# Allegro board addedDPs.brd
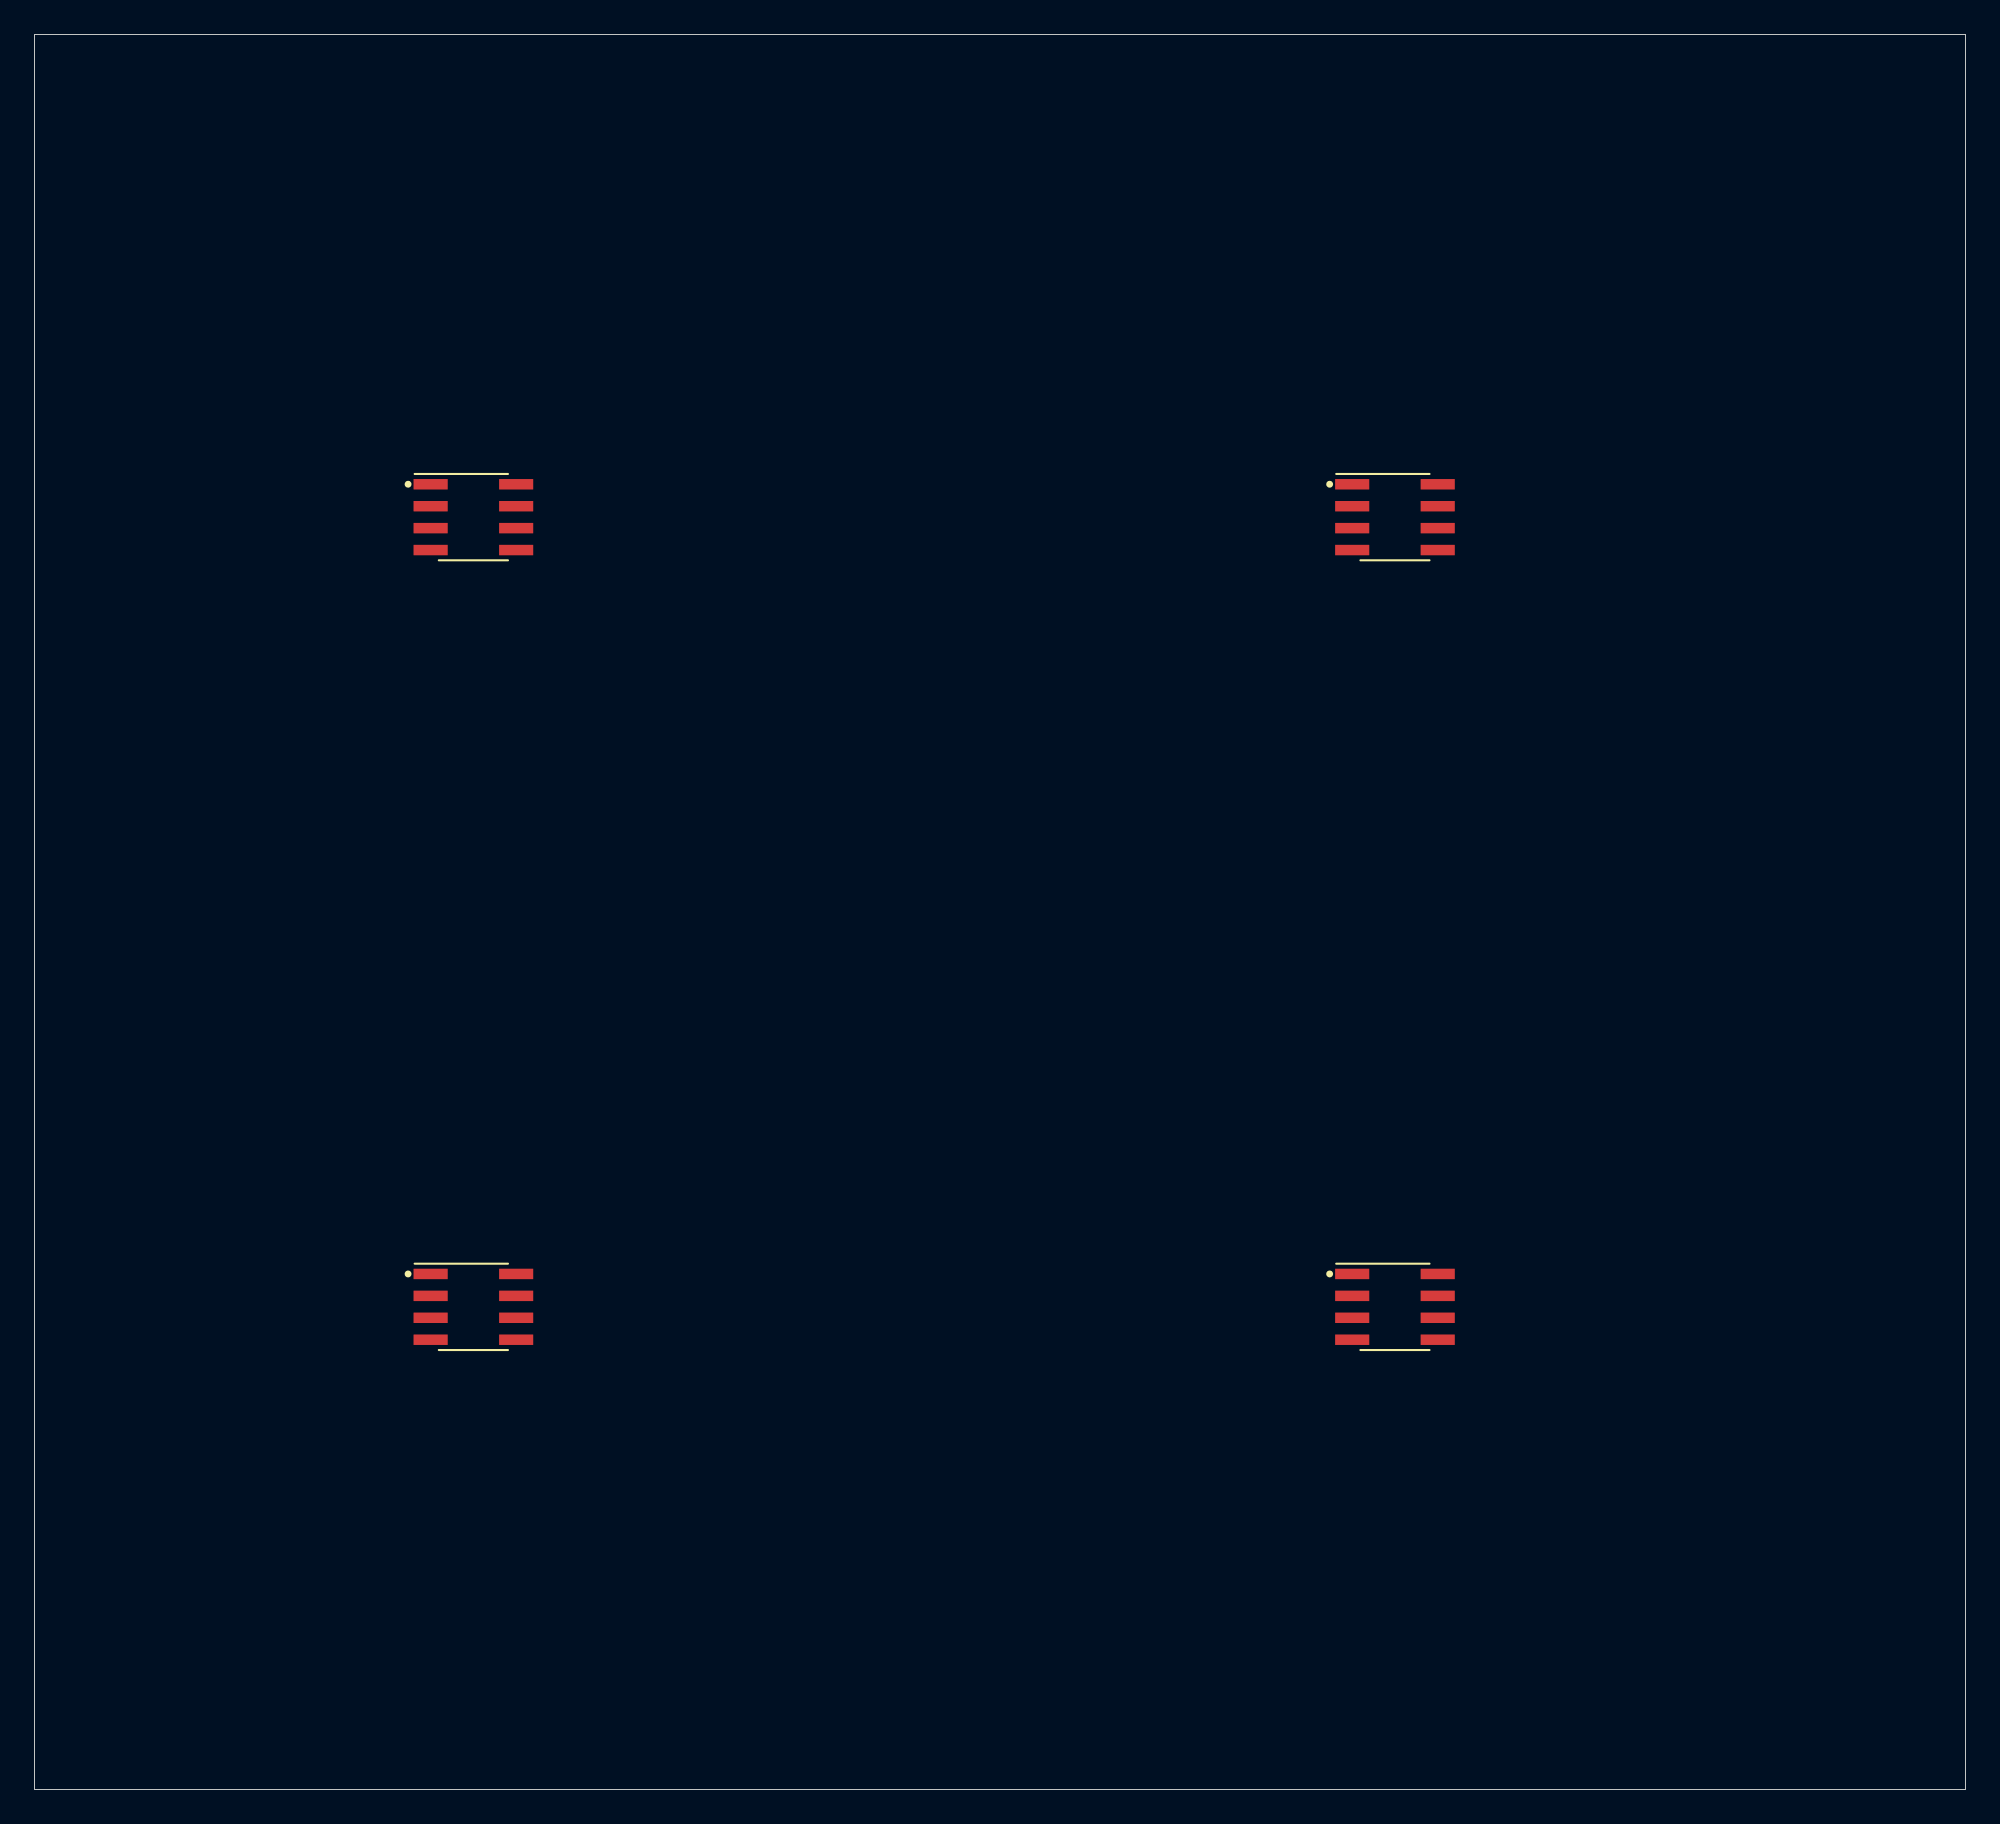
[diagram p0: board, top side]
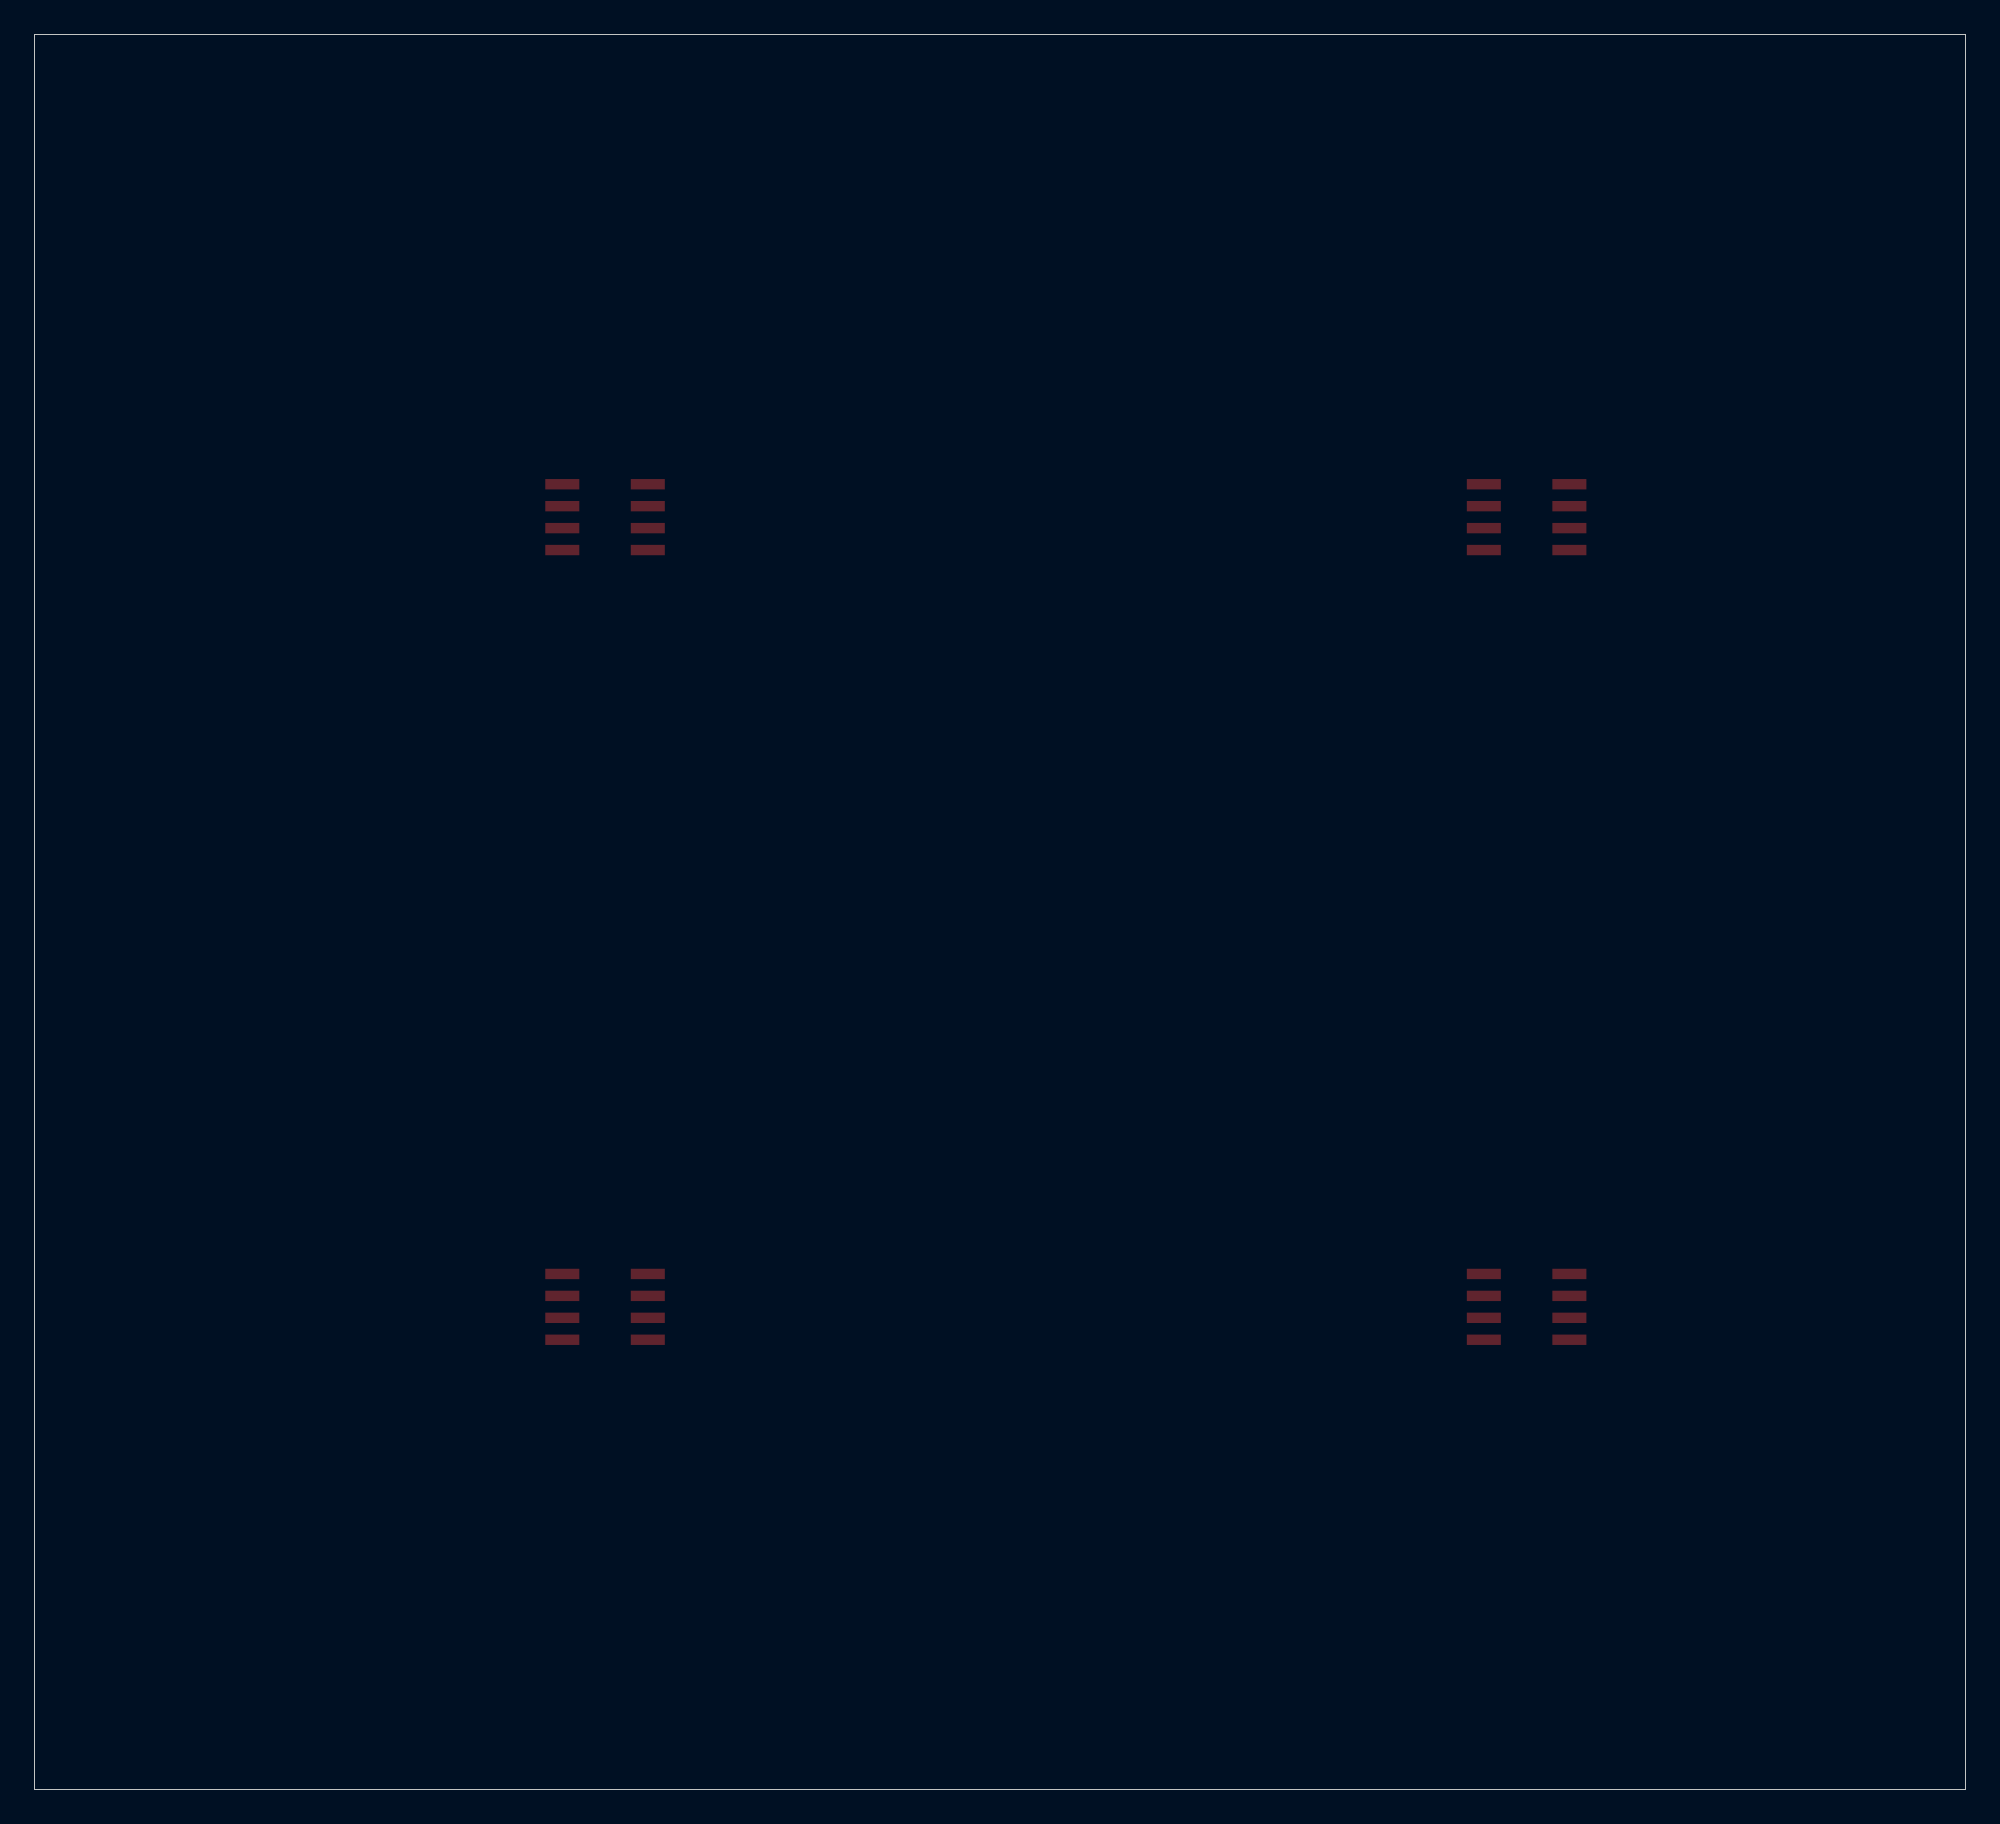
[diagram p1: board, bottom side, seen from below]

Outline 111.76 x 101.6 mm; copper layers: TOP, GND, VCC, BOTTOM. Coordinates in mm from the lower left corner of the outline.
Outline path: 0,101.6 0,0 111.76,0 111.76,101.6 0,101.6

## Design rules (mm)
net group D1: nets D1N D1P
net group D2: nets D2N D2P
net group D3: nets D3N D3P
net group D4: nets D4N D4P

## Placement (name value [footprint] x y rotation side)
U1  DS89C21  [SOIC127P600X175-8L87N]  25.4 73.66 270 top
U2  DS89C21  [SOIC127P600X175-8L87N]  78.74 73.66 270 top
U3  DS89C21  [SOIC127P600X175-8L87N]  78.74 27.94 270 top
U4  DS89C21  [SOIC127P600X175-8L87N]  25.4 27.94 270 top

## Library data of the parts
U1-U4 = DS89C21

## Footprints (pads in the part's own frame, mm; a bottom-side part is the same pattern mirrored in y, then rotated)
SOIC127P600X175-8L87N
  rect 0.6x1.97 smd: 1(-1.905,-2.475) 2(-0.635,-2.475) 3(0.635,-2.475) 4(1.905,-2.475) 5(1.905,2.475) 6(0.635,2.475) 7(-0.635,2.475) 8(-1.905,2.475)

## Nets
GND: U1.4(GND) U2.4(GND) U3.4(GND) U4.4(GND)
VCC: U1.1(VCC) U2.1(VCC) U3.1(VCC) U4.1(VCC)
D1N: U1.5(D_N) U2.7(R_N)
D1P: U1.6(D_P) U2.8(R_P)
D2N: U2.5(D_N) U3.7(R_N)
D2P: U2.6(D_P) U3.8(R_P)
D3N: U3.5(D_N) U4.7(R_N)
D3P: U3.6(D_P) U4.8(R_P)
D4N: U1.7(R_N) U4.5(D_N)
D4P: U1.8(R_P) U4.6(D_P)
X1: U1.2(RO) U2.3(DI)
X2: U2.2(RO) U3.3(DI)
X3: U3.2(RO) U4.3(DI)
X4: U1.3(DI) U4.2(RO)

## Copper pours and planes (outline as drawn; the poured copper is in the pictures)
GND on GND: 0.51,101.09 111.25,101.09 111.25,0.51 0.51,0.51
Net_1 on VCC: 0.51,101.09 111.25,101.09 111.25,0.51 0.51,0.51
